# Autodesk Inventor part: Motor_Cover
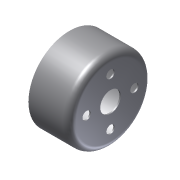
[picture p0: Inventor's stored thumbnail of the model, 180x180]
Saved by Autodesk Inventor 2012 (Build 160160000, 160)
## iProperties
Created: 2012-03
Part Number: Motor_Cover
Material: Default
Document SubType Name: Modeling
Designer: cadcim
Density: 1 g/cm^3
Author: cadcim
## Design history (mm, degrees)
sketch "Sketch4"
  geometry: L1 (0, 0)-(0, 50); L2 (-10, 60)-(-60, 60); L3 (-72.414, 0)-(14.485, 0) reference; L4 (-60, 58)-(-10, 58); L5 (-2, 50)-(-2, 0); L6 (-60, 58)-(-60, 60); L7 (-2, 0)-(0, 0); A1 r 10 centre (-10, 50) between (0, 50) and (-10, 60); A2 r 8 centre (-10, 50) between (-2, 50) and (-10, 58)
  constraints: 12 end point, 4 point on circle, 3 perpendicular, 2 centre point, 1 parallel, 1 tangent, 1 vertical, 2 other
  dimensions: "d25" = 50 distance of L1.start L1.end; "d26" = 50 distance of L2.start L2.end; "d27" = 10 radius of A1; "d28" = 60 distance from line of L1 L2.end; "d31" = 2 distance between parallel lines of L4 L2
revolve "Revolution2" sketch "Sketch4" stored, may be unused: angle "d32" = 90 deg
hole "Hole2" diameter "d35" = 30; stored, may be unused: countersink angle "d39" = 90 deg, drill point angle "d41" = 118 deg; dims "d33" = 10, "d34" = 10, "d36" = 6, "d37" = 4, "d38" = 2, "d40" = 8
sketch "Sketch7"
  geometry: C1 r 6 at (0, 35); 1 further point
  constraints: 1 centre point, 1 vertical alignment
  dimensions: "d42" = 12 diameter of C1; "d43" = 35 distance of point (0, 0) C1.centre
extrude "Extrusion2" cut sketch "Sketch7" distance "d44" = 3; taper "d45" = 0 deg
pattern_circular "Circular Pattern2" dims angle "d47" = 360 deg
body "Solid2"
